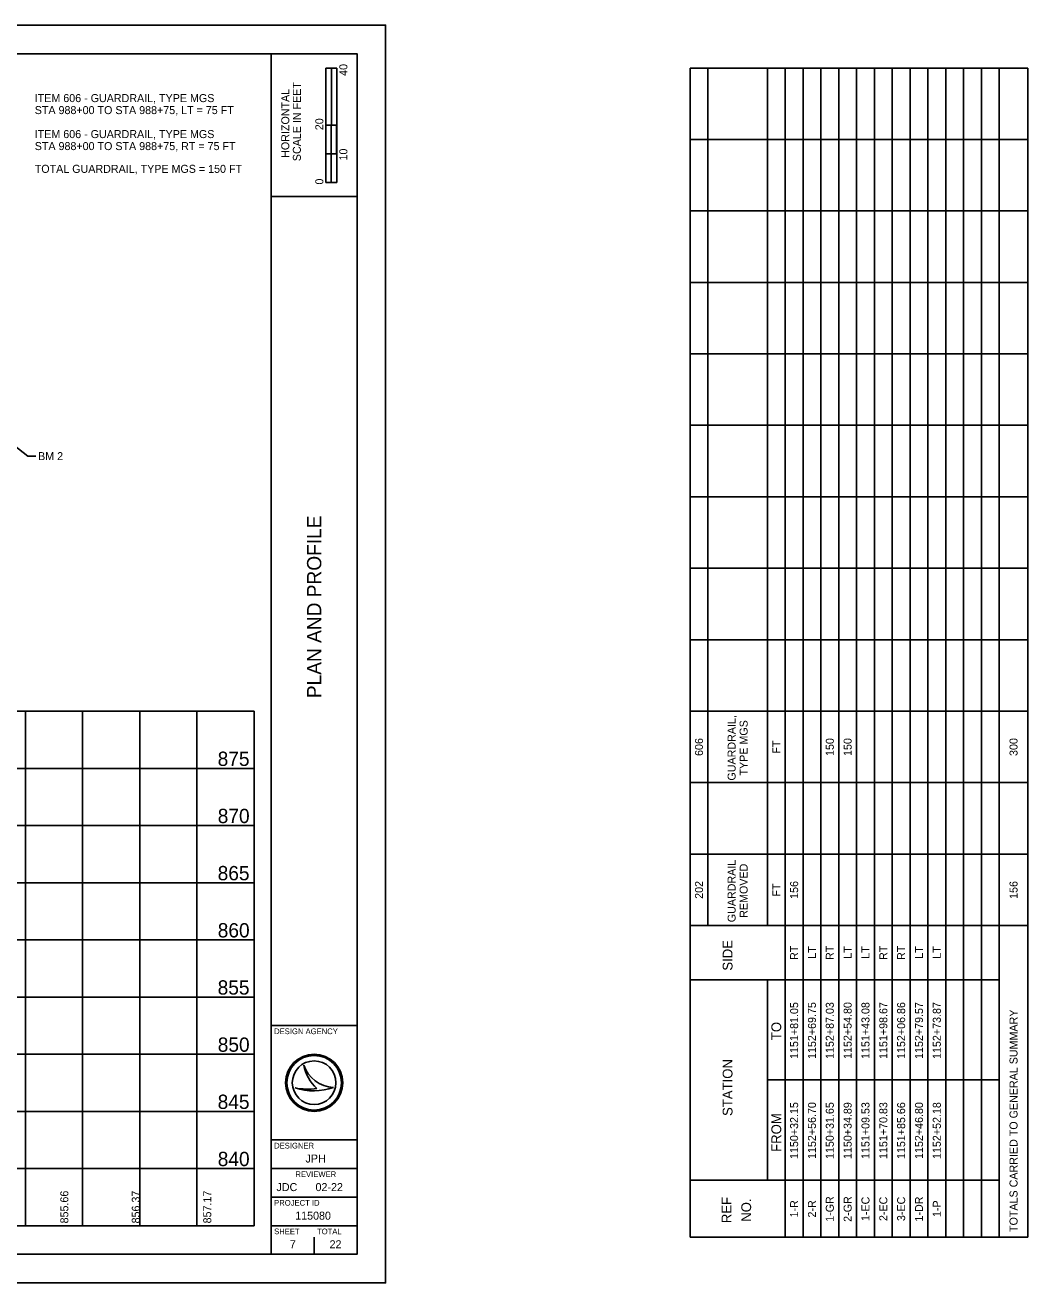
# Model space of a CAD drawing. Extents: x 0 to 905, y 0 to 440.
# Drawn here: x 553.9 to 904.7, y 0 to 440 of the extents above; entities that cross this region are included whole.
import ezdxf

# ---------------------------------------------------------------- set-up
doc = ezdxf.new("R2010")
doc.units = 0
for name, color, linetype in [('DR_X_Culvert', 7, 'Continuous'), ('GE_X_Alignment', 7, 'Continuous'), ('GE_X_Alignment_100_Cardinal_Points', 7, 'Continuous'), ('PF_X_Ground_Line', 7, 'Continuous'), ('TX_X_5', 7, 'Continuous'), ('XS_X_Pavt', 7, 'Continuous')]:
    doc.layers.add(name, color=color, linetype=linetype)

msp = doc.modelspace()

# ---------------------------------------------------------------- linework, layer by layer
at = {"layer": 'DR_X_Culvert'}
msp.add_lwpolyline([(0, 0), (680, 0), (680, 440), (0, 440)], close=True, dxfattribs=at)
at = {"layer": 'GE_X_Alignment'}
for p, q in [((546.66, 295.61), (554.87, 289.22)), ((557.58, 289.22), (554.87, 289.22)), ((554, 20), (554, 200)), ((574, 20), (574, 200)), ((594, 20), (594, 200)), ((614, 20), (614, 200))]:
    msp.add_line(p, q, dxfattribs=at)
at = {"layer": 'PF_X_Ground_Line'}
for p, q in [((640, 10), (640, 430)), ((640, 380), (670, 380)), ((640, 90), (670, 90)), ((640, 50), (670, 50)), ((640, 40), (670, 40)), ((640, 30), (670, 30)), ((640, 20), (670, 20))]:
    msp.add_line(p, q, dxfattribs=at)
msp.add_lwpolyline([(30, 430), (670, 430), (670, 10), (30, 10)], close=True, dxfattribs=at)
at = {"layer": 'TX_X_5'}
for p, q in [((34, 180), (634, 180)), ((34, 160), (634, 160)), ((34, 140), (634, 140)), ((34, 120), (634, 120)), ((34, 100), (634, 100)), ((34, 80), (634, 80)), ((34, 60), (634, 60)), ((34, 40), (634, 40))]:
    msp.add_line(p, q, dxfattribs=at)
at = {"layer": 'XS_X_Pavt'}
for p, q in [((659.13, 385), (659.13, 425)), ((662.88, 425), (659.13, 425)), ((659.13, 405), (659.13, 425)), ((659.13, 425), (661, 425)), ((661, 425), (661.02, 425)), ((661.02, 425), (661.02, 405)), ((662.88, 425), (662.88, 385)), ((786.5, 425), (786.5, 15.98)), ((904.66, 425), (786.5, 425)), ((792.74, 425), (792.74, 125)), ((813.54, 425), (813.54, 125)), ((819.78, 425), (819.78, 15.98)), ((826.02, 425), (826.02, 15.98)), ((832.26, 425), (832.26, 15.98)), ((838.5, 425), (838.5, 15.98)), ((844.74, 425), (844.74, 15.98)), ((850.98, 425), (850.98, 15.98)), ((857.22, 425), (857.22, 15.98)), ((863.46, 425), (863.46, 15.98)), ((869.7, 425), (869.7, 15.98)), ((875.94, 425), (875.94, 15.98)), ((882.18, 425), (882.18, 15.98)), ((888.42, 425), (888.42, 15.98)), ((894.66, 425), (894.66, 15.98)), ((904.66, 425), (904.66, 15.98)), ((661.02, 405), (659.13, 405)), ((662.87, 405), (661, 405)), ((661, 405), (661, 395)), ((662.87, 395), (662.87, 405)), ((904.66, 400), (786.5, 400)), ((661, 395), (659.13, 395)), ((659.13, 395), (659.13, 385)), ((661, 385), (661, 395)), ((661, 395), (662.87, 395)), ((662.88, 385), (659.13, 385)), ((659.13, 385), (661, 385)), ((904.66, 375), (786.5, 375)), ((904.66, 350), (786.5, 350)), ((904.66, 325), (786.5, 325)), ((904.66, 300), (786.5, 300)), ((904.66, 275), (786.5, 275)), ((904.66, 250), (786.5, 250)), ((904.66, 225), (786.5, 225)), ((634, 200), (34, 200)), ((634, 20), (634, 200)), ((904.66, 200), (786.5, 200)), ((904.66, 175), (786.5, 175)), ((904.66, 150), (786.5, 150)), ((904.66, 125), (786.5, 125)), ((786.5, 105.98), (894.66, 105.98)), ((813.54, 105.98), (813.54, 35.98)), ((651.35, 76.19), (651.35, 76.19)), ((813.54, 70.98), (894.66, 70.98)), ((648.34, 68.19), (648.34, 68.19)), ((655, 70), (655, 70)), ((661.75, 68.37), (661.75, 68.37)), ((786.5, 35.98), (894.66, 35.98)), ((34, 20), (634, 20)), ((647.5, 13.5), (647.5, 13.5)), ((655, 10), (655, 16)), ((786.5, 15.98), (904.66, 15.98))]:
    msp.add_line(p, q, dxfattribs=at)
for radius in [10, 9.54, 9.54, 7.64]:
    msp.add_circle((655, 70), radius, dxfattribs=at)
for centre, radius, start, end in [((662.32, 79.95), 11.6, 198.9257, 198.9319), ((666.93, 79.4), 15.91, 191.6379, 191.6421), ((662.32, 79.95), 11.6, 198.9319, 267.1657), ((666.93, 79.4), 15.91, 191.6421, 226.0947), ((654.79, 87.4), 20.26, 251.4576, 290.0832), ((652.96, 93.09), 25.32, 259.4964, 259.4995), ((654.79, 87.4), 20.26, 251.4527, 251.4576), ((652.96, 93.09), 25.32, 259.4995, 276.6672)]:
    msp.add_arc(centre, radius, start, end, dxfattribs=at)

# ---------------------------------------------------------------- texts
at = {"layer": 'GE_X_Alignment'}
for s, p in [('ITEM 606 - GUARDRAIL, TYPE MGS', (557.26, 413.08)), ('STA 988+00 TO STA 988+75, LT = 75 FT', (557.26, 408.88)), ('ITEM 606 - GUARDRAIL, TYPE MGS', (557.26, 400.49)), ('STA 988+00 TO STA 988+75, RT = 75 FT', (557.26, 396.29)), ('TOTAL GUARDRAIL, TYPE MGS = 150 FT', (557.26, 388.33))]:
    msp.add_text(s, height=2.8, dxfattribs=at).set_placement(p)
for s, p in [('GUARDRAIL,', (802.44, 175.72)), ('TYPE MGS', (806.64, 177.49)), ('606', (791.02, 184.33)), ('FT', (818.06, 185.15)), ('150', (836.78, 184.33)), ('150', (843.02, 184.33)), ('300', (901.06, 184.33)), ('GUARDRAIL', (802.44, 126.16)), ('REMOVED', (806.64, 127.71)), ('202', (791.02, 134.34)), ('FT', (818.06, 135.15)), ('156', (824.3, 134.33)), ('156', (901.06, 134.33)), ('RT', (824.3, 112.96)), ('LT', (830.54, 113.39)), ('RT', (836.78, 112.96)), ('LT', (843.02, 113.39)), ('LT', (849.26, 113.39)), ('RT', (855.5, 112.96)), ('RT', (861.74, 112.96)), ('LT', (867.98, 113.39)), ('LT', (874.22, 113.39)), ('1151+81.05', (824.3, 78.32)), ('1152+69.75', (830.54, 78.32)), ('1152+87.03', (836.78, 78.33)), ('1152+54.80', (843.02, 78.34)), ('1151+43.08', (849.26, 78.33)), ('1151+98.67', (855.5, 78.33)), ('1152+06.86', (861.74, 78.33)), ('1152+79.57', (867.98, 78.33)), ('1152+73.87', (874.22, 78.33)), ('1150+32.15', (824.3, 43.32)), ('1152+56.70', (830.54, 43.34)), ('1150+31.65', (836.78, 43.32)), ('1150+34.89', (843.02, 43.31)), ('1151+09.53', (849.26, 43.33)), ('1151+70.83', (855.5, 43.33)), ('1151+85.66', (861.74, 43.31)), ('1152+46.80', (867.98, 43.34)), ('1152+52.18', (874.22, 43.33)), ('1-R', (824.3, 22.86)), ('2-R', (830.54, 22.86)), ('1-GR', (836.78, 21.34)), ('2-GR', (843.02, 21.34)), ('1-EC', (849.26, 21.61)), ('2-EC', (855.5, 21.61)), ('3-EC', (861.74, 21.61)), ('1-DR', (867.98, 21.45)), ('1-P', (874.22, 23.03))]:
    msp.add_text(s, height=2.8, rotation=90, dxfattribs=at).set_placement(p)
at = {"layer": 'GE_X_Alignment_100_Cardinal_Points'}
msp.add_text('BM 2', height=2.8, dxfattribs=at).set_placement((558.42, 287.82))
for s, p in [('855.66', (569, 20.79)), ('856.37', (594, 20.79)), ('857.17', (619, 20.79))]:
    msp.add_text(s, height=2.8, rotation=90, dxfattribs=at).set_placement(p)
at = {"layer": 'XS_X_Pavt'}
for s, height, p in [('40', 2.8, (666.61, 422.25)), ('SCALE IN FEET', 2.8, (650.35, 392.41)), ('HORIZONTAL', 2.8, (646.3, 393.58)), ('20', 2.8, (658.21, 403.25)), ('10', 2.8, (666.61, 392.65)), ('0', 2.8, (658.21, 384.23)), ('PLAN AND PROFILE', 5, (657.5, 204.55)), ('SIDE', 3.435, (801.34, 109.22)), ('TOTALS CARRIED TO GENERAL SUMMARY', 2.8, (901.06, 17.8)), ('TO', 3.435, (818.38, 84.91)), ('STATION', 3.435, (801.34, 58.38)), ('FROM', 3.435, (818.38, 45.81)), ('REF', 3.436, (800.99, 20.88)), ('NO.', 3.436, (807.86, 21.36))]:
    msp.add_text(s, height=height, rotation=90, dxfattribs=at).set_placement(p)
for s, height, p in [('875', 5, (621.24, 180.84)), ('870', 5, (621.27, 160.84)), ('865', 5, (621.24, 140.84)), ('860', 5, (621.27, 120.84)), ('855', 5, (621.24, 100.84)), ('DESIGN AGENCY', 2, (641, 87)), ('850', 5, (621.27, 80.84)), ('845', 5, (621.24, 60.84)), ('DESIGNER', 2, (641, 47)), ('840', 5, (621.27, 40.84)), ('JPH', 2.8, (651.97, 42.1)), ('REVIEWER', 2, (648.44, 37)), ('JDC', 2.8, (641.82, 32.1)), ('02-22', 2.8, (655.48, 32.1)), ('PROJECT ID', 2, (641, 27)), ('115080', 2.8, (648.37, 22.1)), ('SHEET', 2, (641, 17)), ('TOTAL', 2, (656, 17)), ('7', 2.8, (646.48, 12.1)), ('22', 2.8, (660.39, 12.1))]:
    msp.add_text(s, height=height, dxfattribs=at).set_placement(p)

doc.saveas('drawing.dxf')
